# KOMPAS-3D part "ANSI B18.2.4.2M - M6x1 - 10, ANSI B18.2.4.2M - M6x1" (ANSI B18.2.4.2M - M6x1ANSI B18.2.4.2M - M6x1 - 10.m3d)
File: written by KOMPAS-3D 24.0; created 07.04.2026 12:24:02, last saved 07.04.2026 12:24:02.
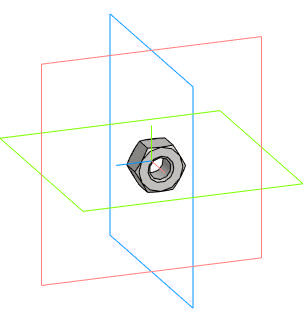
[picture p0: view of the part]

Document properties: Автор: Main; Полное имя файла: D:\DN.ru Аутсерс\Стекло смотровое DN.ru\Исходники\Стекло смотровое DN.ru SG2-34G-F тип В ГОСТ 21836-2021 Ду15 Ру40, углеродистая сталь, фланцевое\ANSI B18.2.4.2M - M6x1ANSI B18.2.4.2M - M6x1 - 10.m3d

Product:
- Body: Solid1  | qty 1
- Part/product: ANSI B18.2.4.2M - M6x1 - 10  | designation ANSI B18.2.4.2M - M6x1
    Комментарий: Типы метрических   шестигранных гаек   2
    additional columns: Сталь, мягкая

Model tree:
1. Solid1  (labels: Solid1)

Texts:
  ANSI B18.2.4.2M - M6x1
